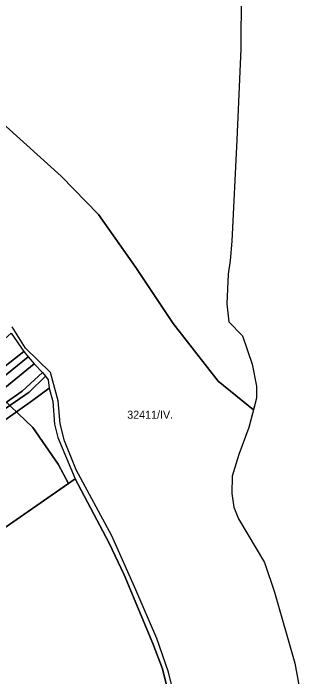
# Model space of a CAD drawing. Extents: x -532083 to -529270, y -1180561 to -1176456.
# Drawn here: x -529940.1 to -529760.8, y -1179394.7 to -1178980.2 of the extents above; entities that cross this region are included whole.
import ezdxf

# ---------------------------------------------------------------- set-up
doc = ezdxf.new("R2010")
doc.units = 0
for name, color, linetype in [('95560013', 7, 'Continuous'), ('95590013', 7, 'Continuous'), ('95620013', 7, 'Continuous'), ('95660013', 7, 'Continuous')]:
    doc.layers.add(name, color=color, linetype=linetype)

msp = doc.modelspace()

# ---------------------------------------------------------------- linework, layer by layer
at = {"layer": '95560013'}
for points in [[(-529797.8273, -1178967.16945), (-529798.1793, -1179002.39145), (-529800.6303, -1179059.25145), (-529803.6643, -1179122.65845), (-529804.7883, -1179134.70545), (-529806.0063, -1179143.15845), (-529806.9423, -1179161.75445), (-529805.5713, -1179172.90345), (-529797.1663, -1179181.64045), (-529791.0533, -1179199.42245), (-529788.3023, -1179213.06445), (-529788.3023, -1179220.72845), (-529793.0853, -1179238.91945), (-529799.2923, -1179255.84645), (-529803.5603, -1179269.46645), (-529803.7543, -1179280.16645), (-529802.5903, -1179288.72745), (-529799.6803, -1179296.12145), (-529783.3873, -1179323.35945), (-529777.1383, -1179341.82345), (-529764.4693, -1179386.20145), (-529760.7663, -1179406.72845)], [(-529838.8543, -1179409.79145), (-529843.3593, -1179391.84445), (-529850.6073, -1179370.90245), (-529863.6463, -1179340.31145), (-529878.5783, -1179306.76745), (-529900.7973, -1179265.40645), (-529908.2163, -1179247.38645), (-529910.9503, -1179236.61445), (-529912.1213, -1179222.31645), (-529917.0023, -1179204.68845), (-529932.4273, -1179189.41045), (-529940.8363, -1179176.09945)]]:
    msp.add_lwpolyline(points, dxfattribs=at)
at = {"layer": '95590013'}
for points in [[(-530031.2433, -1179259.32545), (-530038.8283, -1179247.98845), (-530005.7933, -1179227.68445), (-529984.7553, -1179214.29745), (-529975.1793, -1179207.36845), (-529953.6703, -1179190.83145), (-529941.4043, -1179180.01245), (-529933.6013, -1179191.50545), (-529965.7593, -1179216.66045), (-529999.0423, -1179239.02445), (-530019.4523, -1179251.78045)], [(-530030.3143, -1179263.82845), (-530057.5593, -1179279.82345), (-530071.1823, -1179288.67545), (-530104.3233, -1179309.96545), (-530106.1373, -1179307.07545), (-530083.1023, -1179292.24645), (-530060.6553, -1179276.40745), (-530031.2433, -1179259.32545), (-530019.4523, -1179251.78045), (-529999.0423, -1179239.02445), (-529965.7593, -1179216.66045), (-529933.6013, -1179191.50545), (-529930.9443, -1179194.74045), (-529961.9913, -1179219.96745), (-529995.3293, -1179243.64045)], [(-530021.0433, -1179264.00945), (-530053.2823, -1179282.75345), (-530085.1103, -1179303.97045), (-530101.1233, -1179315.31545), (-530104.3233, -1179309.96545), (-530071.1823, -1179288.67545), (-530057.5593, -1179279.82345), (-530030.3143, -1179263.82845), (-529995.3293, -1179243.64045), (-529961.9913, -1179219.96745), (-529930.9443, -1179194.74045), (-529927.0553, -1179199.11845), (-529947.7473, -1179215.99645), (-529971.3233, -1179232.20145), (-529993.3723, -1179247.09345), (-530002.9353, -1179252.93945), (-530010.5233, -1179257.57845)], [(-530023.5083, -1179274.10245), (-530041.9883, -1179285.63745), (-530065.8083, -1179301.08645), (-530096.9623, -1179322.27245), (-530101.1233, -1179315.31545), (-530085.1103, -1179303.97045), (-530053.2823, -1179282.75345), (-530021.0433, -1179264.00945), (-530010.5233, -1179257.57845), (-530009.5853, -1179259.11145), (-530007.3723, -1179262.61045), (-529999.8413, -1179257.84745), (-530002.0543, -1179254.34845), (-530002.9353, -1179252.93945), (-529993.3723, -1179247.09345), (-529971.3233, -1179232.20145), (-529947.7473, -1179215.99645), (-529927.0553, -1179199.11845), (-529921.8373, -1179204.54245), (-529934.6493, -1179216.21545), (-529970.6693, -1179241.39945), (-529996.4283, -1179257.38545), (-530008.3123, -1179265.03945)], [(-530014.3293, -1179272.49645), (-530043.1043, -1179291.10945), (-530044.9073, -1179288.90945), (-530047.9803, -1179291.42845), (-530048.6303, -1179291.94945), (-530047.3313, -1179293.64245), (-530071.1463, -1179309.53245), (-530094.8293, -1179325.26845), (-530096.9623, -1179322.27245), (-530065.8083, -1179301.08645), (-530041.9883, -1179285.63745), (-530023.5083, -1179274.10245), (-530008.3123, -1179265.03945), (-529996.4283, -1179257.38545), (-529970.6693, -1179241.39945), (-529934.6493, -1179216.21545), (-529921.8373, -1179204.54245), (-529919.9403, -1179206.92145), (-529930.2823, -1179216.87245), (-529953.8593, -1179233.07745), (-529978.0913, -1179248.18845)], [(-530063.9603, -1179312.82845), (-530092.2873, -1179329.05845), (-530094.8293, -1179325.26845), (-530071.1463, -1179309.53245), (-530047.3313, -1179293.64245), (-530043.6943, -1179297.81245), (-530043.1753, -1179297.29045), (-530040.1023, -1179294.77245), (-530043.1043, -1179291.10945), (-530014.3293, -1179272.49645), (-529978.0913, -1179248.18845), (-529953.8593, -1179233.07745), (-529930.2823, -1179216.87245), (-529919.9403, -1179206.92145), (-529918.4223, -1179209.30145), (-529917.7583, -1179214.44045), (-529928.0993, -1179222.12745), (-529954.9243, -1179241.14445), (-529986.7523, -1179261.74345), (-530001.7423, -1179268.95245), (-530010.9823, -1179275.33845), (-530029.8733, -1179290.58145)], [(-530077.6063, -1179385.04845), (-530085.4243, -1179354.90345), (-530092.2873, -1179329.05845), (-530063.9603, -1179312.82845), (-530029.8733, -1179290.58145), (-530010.9823, -1179275.33845), (-530001.7423, -1179268.95245), (-529986.7523, -1179261.74345), (-529954.9243, -1179241.14445), (-529928.0993, -1179222.12745), (-529917.7583, -1179214.44045), (-529915.5493, -1179222.72845), (-529914.4343, -1179236.84645), (-529912.3443, -1179245.23345), (-529901.4753, -1179271.09245), (-529972.7423, -1179320.39245), (-529982.7213, -1179327.40045), (-529999.0633, -1179336.53645), (-530035.7073, -1179357.84445)]]:
    msp.add_lwpolyline(points, close=True, dxfattribs=at)
at = {"layer": '95620013'}
msp.add_lwpolyline([(-530072.7633, -1179412.96245), (-530077.6063, -1179385.04845), (-530035.7073, -1179357.84445), (-529999.0633, -1179336.53645), (-529982.7213, -1179327.40045), (-529972.7423, -1179320.39245), (-529901.4753, -1179271.09245), (-529880.2713, -1179311.16145), (-529870.9293, -1179331.00845), (-529852.9773, -1179374.00745), (-529847.0203, -1179389.83145), (-529841.2623, -1179413.21145)], dxfattribs=at)
at = {"layer": '95660013'}
for points in [[(-529841.2623, -1179413.21145), (-529847.0203, -1179389.83145), (-529852.9773, -1179374.00745), (-529870.9293, -1179331.00845), (-529880.2713, -1179311.16145), (-529901.4753, -1179271.09245), (-529905.5843, -1179273.93445), (-529912.1253, -1179262.00045), (-529927.8753, -1179239.00045), (-529951.3123, -1179217.00045), (-529979.3753, -1179204.00045), (-529997.8123, -1179194.00045), (-530000.0003, -1179191.00045), (-530011.8753, -1179184.00045), (-530035.8123, -1179169.00045), (-530061.3123, -1179147.00045), (-530077.5003, -1179128.00045), (-530092.0003, -1179106.00045), (-530112.0003, -1179062.00045), (-530129.8753, -1179017.00045), (-530131.6253, -1178999.00045), (-530140.1253, -1178957.00045)], [(-529797.8273, -1178967.16945), (-529798.1793, -1179002.39145), (-529800.6303, -1179059.25145), (-529803.6643, -1179122.65845), (-529804.7883, -1179134.70545), (-529806.0063, -1179143.15845), (-529806.9423, -1179161.75445), (-529805.5713, -1179172.90345), (-529797.1663, -1179181.64045), (-529791.0533, -1179199.42245), (-529788.3023, -1179213.06445), (-529788.3023, -1179220.72845), (-529790.2273, -1179228.04845), (-529812.3123, -1179210.00045), (-529840.3753, -1179174.00045), (-529863.6873, -1179139.00045), (-529886.8753, -1179106.00045), (-529910.1873, -1179082.00045), (-529944.5003, -1179051.00045), (-529970.1873, -1179024.00045), (-530000.0003, -1178972.00045)], [(-530000.0003, -1178972.00045), (-529970.1873, -1179024.00045), (-529944.5003, -1179051.00045), (-529910.1873, -1179082.00045), (-529886.8753, -1179106.00045), (-529863.6873, -1179139.00045), (-529840.3753, -1179174.00045), (-529812.3123, -1179210.00045), (-529790.2273, -1179228.04845), (-529793.0853, -1179238.91945), (-529799.2923, -1179255.84645), (-529803.5603, -1179269.46645), (-529803.7543, -1179280.16645), (-529802.5903, -1179288.72745), (-529799.6803, -1179296.12145), (-529783.3873, -1179323.35945), (-529777.1383, -1179341.82345), (-529764.4693, -1179386.20145), (-529760.7663, -1179406.72845)], [(-529951.3123, -1179217.00045), (-529927.8753, -1179239.00045), (-529912.1253, -1179262.00045), (-529905.5843, -1179273.93445), (-529972.7423, -1179320.39245)], [(-529972.7423, -1179320.39245), (-529905.5843, -1179273.93445), (-529901.4753, -1179271.09245), (-529880.2713, -1179311.16145), (-529870.9293, -1179331.00845), (-529852.9773, -1179374.00745), (-529847.0203, -1179389.83145), (-529841.2623, -1179413.21145)]]:
    msp.add_lwpolyline(points, dxfattribs=at)

# ---------------------------------------------------------------- texts
msp.add_text('32411/IV.', height=5, rotation=360, dxfattribs=at).set_placement((-529869.0188, -1179233.49872))

doc.saveas('drawing.dxf')
